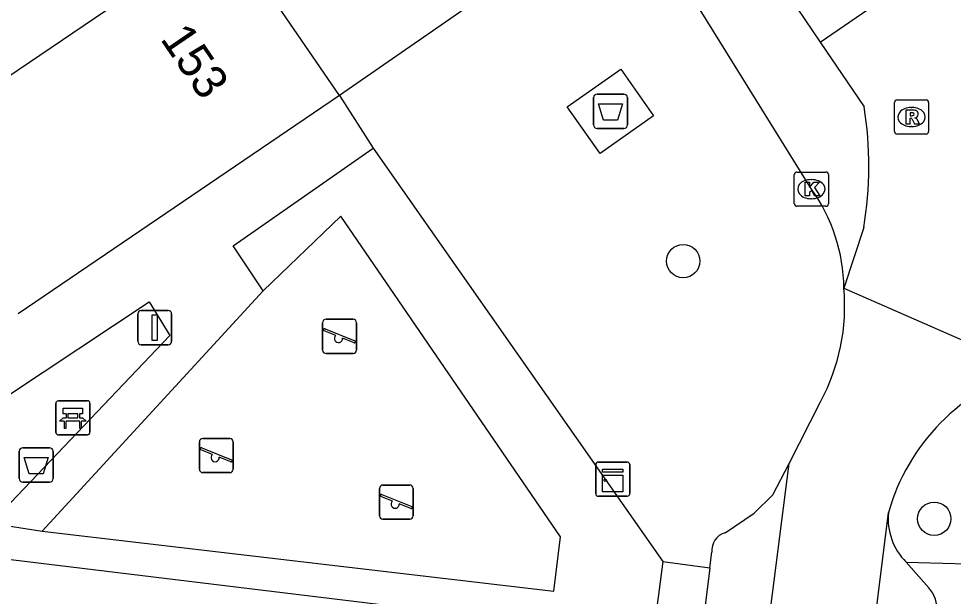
# Model space of a CAD drawing. Extents: x 158087 to 159494, y 382905 to 383981.
# Drawn here: x 158364.19 to 158391.56, y 383387.55 to 383404.47 of the extents above; entities that cross this region are included whole.
import ezdxf

# ---------------------------------------------------------------- set-up
doc = ezdxf.new("R2010")
doc.units = 0
for name, color, linetype in [('IMGEO_Afval_apart_plaats', 7, 'Continuous'), ('IMGEO_Afvalbak', 7, 'Continuous'), ('IMGEO_Bank', 7, 'Continuous'), ('IMGEO_Boom', 7, 'Continuous'), ('IMGEO_Groenvoorziening', 7, 'Continuous'), ('IMGEO_Kast', 7, 'Continuous'), ('IMGEO_Kolk', 7, 'Continuous'), ('IMGEO_Pand', 7, 'Continuous'), ('IMGEO_Pand_nummerreeks', 7, 'Continuous'), ('IMGEO_Rijbaan_lokaal_gesloten', 7, 'Continuous'), ('IMGEO_Rijbaan_lokaal_open', 7, 'Continuous'), ('IMGEO_Rioolput', 7, 'Continuous'), ('IMGEO_Speelvoorziening', 7, 'Continuous'), ('IMGEO_Verkeersbordpaal', 7, 'Continuous'), ('IMGEO_Voetpad_gesloten', 7, 'Continuous'), ('IMGEO_Voetpad_open', 7, 'Continuous')]:
    doc.layers.add(name, color=color, linetype=linetype)

msp = doc.modelspace()

# ---------------------------------------------------------------- linework, layer by layer
at = {"layer": 'IMGEO_Afval_apart_plaats'}
for p, q in [((158381.024, 383401.357), (158381.024, 383402.157)), ((158381.024, 383402.157), (158381.024, 383401.357)), ((158381.124, 383402.257), (158381.914, 383402.257)), ((158381.914, 383402.257), (158381.124, 383402.257)), ((158382.014, 383402.157), (158382.014, 383401.357)), ((158382.014, 383401.357), (158382.014, 383402.157)), ((158381.914, 383401.257), (158381.124, 383401.257)), ((158381.124, 383401.257), (158381.914, 383401.257))]:
    msp.add_line(p, q, dxfattribs=at)
msp.add_lwpolyline([(158381.167, 383401.971), (158381.871, 383401.971), (158381.722, 383401.501), (158381.316, 383401.501), (158381.167, 383401.971)], dxfattribs=at)
for centre, start, end in [((158381.124, 383402.157), 90, 180), ((158381.124, 383402.157), 90, 180), ((158381.914, 383402.157), 0, 90), ((158381.914, 383402.157), 360, 90), ((158381.124, 383401.357), 180, 270), ((158381.124, 383401.357), 180, 270), ((158381.914, 383401.357), 270, 0), ((158381.914, 383401.357), 270, 0)]:
    msp.add_arc(centre, 0.1, start, end, dxfattribs=at)
at = {"layer": 'IMGEO_Afvalbak'}
for p, q in [((158364.202, 383390.996), (158364.202, 383391.796)), ((158364.202, 383391.796), (158364.202, 383390.996)), ((158364.302, 383391.896), (158365.092, 383391.896)), ((158365.092, 383391.896), (158364.302, 383391.896)), ((158365.192, 383391.796), (158365.192, 383390.996)), ((158365.192, 383390.996), (158365.192, 383391.796)), ((158365.092, 383390.896), (158364.302, 383390.896)), ((158364.302, 383390.896), (158365.092, 383390.896))]:
    msp.add_line(p, q, dxfattribs=at)
msp.add_lwpolyline([(158364.345, 383391.61), (158365.049, 383391.61), (158364.9, 383391.14), (158364.494, 383391.14), (158364.345, 383391.61)], dxfattribs=at)
for centre, start, end in [((158364.302, 383391.796), 90, 180), ((158364.302, 383391.796), 90, 180), ((158365.092, 383391.796), 0, 90), ((158365.092, 383391.796), 360, 90), ((158364.302, 383390.996), 180, 270), ((158364.302, 383390.996), 180, 270), ((158365.092, 383390.996), 270, 0), ((158365.092, 383390.996), 270, 0)]:
    msp.add_arc(centre, 0.1, start, end, dxfattribs=at)
at = {"layer": 'IMGEO_Bank'}
for p, q in [((158365.272, 383392.351), (158365.272, 383393.192)), ((158365.272, 383393.192), (158365.272, 383392.351)), ((158365.347, 383393.276), (158366.188, 383393.276)), ((158366.188, 383393.276), (158365.347, 383393.276)), ((158366.272, 383393.201), (158366.272, 383392.36)), ((158366.272, 383392.36), (158366.272, 383393.201)), ((158365.581, 383392.782), (158365.581, 383392.888)), ((158365.625, 383392.888), (158365.625, 383392.782)), ((158365.913, 383392.894), (158365.631, 383392.894)), ((158365.919, 383392.782), (158365.919, 383392.888)), ((158365.963, 383392.888), (158365.963, 383392.782)), ((158365.969, 383392.674), (158365.576, 383392.674)), ((158365.631, 383392.776), (158365.913, 383392.776)), ((158366.197, 383392.276), (158365.356, 383392.276)), ((158365.356, 383392.276), (158366.197, 383392.276))]:
    msp.add_line(p, q, dxfattribs=at)
for points in [[(158365.575, 383392.894), (158365.489, 383392.894), (158365.489, 383393.055), (158366.052, 383393.055), (158366.052, 383392.894), (158365.969, 383392.894)], [(158365.519, 383392.674), (158365.377, 383392.674), (158365.489, 383392.776), (158365.575, 383392.776)], [(158365.569, 383392.667), (158365.569, 383392.46), (158365.526, 383392.46), (158365.526, 383392.667)], [(158365.969, 383392.776), (158366.052, 383392.776), (158366.164, 383392.674), (158366.025, 383392.674)], [(158366.019, 383392.667), (158366.019, 383392.46), (158365.975, 383392.46), (158365.975, 383392.667)]]:
    msp.add_lwpolyline(points, dxfattribs=at)
for centre, radius, start, end in [((158365.35, 383393.198), 0.0779, 92.4484, 184.2845), ((158365.35, 383393.198), 0.0779, 92.4484, 184.2845), ((158366.194, 383393.198), 0.0779, 2.4484, 94.2845), ((158366.194, 383393.198), 0.0779, 2.4484, 94.2845), ((158365.574, 383392.887), 0.00671, 2.8957, 87.1043), ((158365.631, 383392.887), 0.00671, 92.8957, 177.1043), ((158365.913, 383392.887), 0.00671, 2.8957, 87.1043), ((158365.97, 383392.887), 0.00671, 92.8957, 177.1043), ((158365.519, 383392.667), 0.00671, 2.8957, 87.1043), ((158365.576, 383392.667), 0.00671, 92.8957, 177.1043), ((158365.574, 383392.783), 0.00671, 272.8957, 357.1043), ((158365.631, 383392.783), 0.00671, 182.8957, 267.1043), ((158365.913, 383392.783), 0.00671, 272.8957, 357.1043), ((158365.97, 383392.783), 0.00671, 182.8957, 267.1043), ((158365.968, 383392.667), 0.00671, 2.8957, 87.1043), ((158366.025, 383392.667), 0.00671, 92.8957, 177.1043), ((158365.35, 383392.354), 0.0779, 182.4484, 274.2845), ((158365.35, 383392.354), 0.0779, 182.4484, 274.2845), ((158366.194, 383392.354), 0.0779, 272.4484, 4.2845), ((158366.194, 383392.354), 0.0779, 272.4484, 4.2845)]:
    msp.add_arc(centre, radius, start, end, dxfattribs=at)
at = {"layer": 'IMGEO_Boom'}
for centre in [(158383.648, 383397.369), (158391.001, 383389.819)]:
    msp.add_circle(centre, 0.489, dxfattribs=at)
at = {"layer": 'IMGEO_Groenvoorziening'}
msp.add_lwpolyline([(158364.869, 383389.459), (158379.856, 383387.7), (158380.054, 383389.292), (158373.623, 383398.689), (158371.344, 383396.5)], dxfattribs=at)
at = {"layer": 'IMGEO_Kast'}
for p, q in [((158381.161, 383391.481), (158382.002, 383391.481)), ((158382.002, 383391.481), (158381.161, 383391.481)), ((158381.086, 383390.556), (158381.086, 383391.397)), ((158381.086, 383391.397), (158381.086, 383390.556)), ((158382.086, 383391.406), (158382.086, 383390.565)), ((158382.086, 383390.565), (158382.086, 383391.406)), ((158382.011, 383390.481), (158381.17, 383390.481)), ((158381.17, 383390.481), (158382.011, 383390.481))]:
    msp.add_line(p, q, dxfattribs=at)
for points in [[(158381.281, 383391.271), (158381.881, 383391.271), (158381.881, 383391.186), (158381.281, 383391.186), (158381.281, 383391.271)], [(158381.281, 383391.096), (158381.881, 383391.096), (158381.881, 383390.607), (158381.281, 383390.607), (158381.281, 383391.096)]]:
    msp.add_lwpolyline(points, dxfattribs=at)
msp.add_circle((158381.365, 383390.945), 0.0377, dxfattribs=at)
for centre, start, end in [((158381.164, 383391.403), 92.4484, 184.2845), ((158381.164, 383391.403), 92.4484, 184.2845), ((158382.008, 383391.403), 2.4484, 94.2845), ((158382.008, 383391.403), 2.4484, 94.2845), ((158381.164, 383390.559), 182.4484, 274.2845), ((158381.164, 383390.559), 182.4484, 274.2845), ((158382.008, 383390.559), 272.4484, 4.2845), ((158382.008, 383390.559), 272.4484, 4.2845)]:
    msp.add_arc(centre, 0.0779, start, end, dxfattribs=at)
at = {"layer": 'IMGEO_Kolk'}
for p, q in [((158386.978, 383399.976), (158387.83, 383399.976)), ((158386.903, 383399.05), (158386.903, 383399.902)), ((158387.391, 383399.756), (158387.416, 383399.756)), ((158387.904, 383399.902), (158387.904, 383399.05)), ((158387.414, 383399.196), (158387.389, 383399.196)), ((158387.83, 383398.976), (158386.978, 383398.976))]:
    msp.add_line(p, q, dxfattribs=at)
for points in [[(158386.978, 383399.976), (158387.83, 383399.976)], [(158386.903, 383399.05), (158386.903, 383399.902)], [(158387.904, 383399.902), (158387.904, 383399.05)], [(158387.224, 383399.676), (158387.347, 383399.676), (158387.347, 383399.525), (158387.477, 383399.676), (158387.641, 383399.676), (158387.495, 383399.525), (158387.648, 383399.276), (158387.496, 383399.276), (158387.411, 383399.44), (158387.347, 383399.373), (158387.347, 383399.276), (158387.224, 383399.276), (158387.224, 383399.676)], [(158387.83, 383398.976), (158386.978, 383398.976)]]:
    msp.add_lwpolyline(points, dxfattribs=at)
for centre, start, end in [((158386.98, 383399.9), 91.552, 178.448), ((158386.98, 383399.9), 91.552, 178.448), ((158387.828, 383399.9), 1.552, 88.448), ((158387.828, 383399.9), 1.552, 88.448), ((158386.98, 383399.052), 181.552, 268.448), ((158386.98, 383399.052), 181.552, 268.448), ((158387.828, 383399.052), 271.552, 358.448), ((158387.828, 383399.052), 271.552, 358.448)]:
    msp.add_arc(centre, 0.0765, start, end, dxfattribs=at)
for centre, major_axis, ratio, start_param, end_param in [((158387.39, 383399.476), (-0.387, 0.002), 0.722429, 4.712389, 7.853982), ((158387.415, 383399.476), (-0.39, 0.002), 0.717154, 1.570796, 4.712389)]:
    msp.add_ellipse(centre, major_axis=major_axis, ratio=ratio, start_param=start_param, end_param=end_param, dxfattribs=at)
at = {"layer": 'IMGEO_Pand'}
for points in [[(158362.89, 383402.113), (158370.246, 383407.093)], [(158373.579, 383402.215), (158370.246, 383407.093)], [(158373.579, 383402.215), (158364.168, 383395.827)]]:
    msp.add_lwpolyline(points, dxfattribs=at)
at = {"layer": 'IMGEO_Rijbaan_lokaal_gesloten'}
for points in [[(158376.95, 383419.335), (158377.778, 383418.395), (158387.664, 383403.781)], [(158387.664, 383403.781), (158391.54, 383406.45)], [(158387.664, 383403.781), (158388.948, 383401.883)], [(158388.936, 383398.348), (158388.354, 383396.576)], [(158388.354, 383396.576), (158393.787, 383394.193)]]:
    msp.add_lwpolyline(points, dxfattribs=at)
msp.add_arc((158378.281, 383400.152), 10.807, 350.3922, 9.2188, dxfattribs=at)
at = {"layer": 'IMGEO_Rijbaan_lokaal_open'}
for points in [[(158386.755, 383391.434), (158387.668, 383393.247)], [(158379.524, 383334.921), (158386.755, 383391.434)], [(158382.338, 383331.19), (158389.661, 383390.001)]]:
    msp.add_lwpolyline(points, dxfattribs=at)
for centre, radius, start, end in [((158382.524, 383396.042), 5.854, 331.4801, 5.2322), ((158395.528, 383388.353), 6.094, 106.5991, 164.3101)]:
    msp.add_arc(centre, radius, start, end, dxfattribs=at)
at = {"layer": 'IMGEO_Rioolput'}
for p, q in [((158389.836, 383401.164), (158389.836, 383402.016)), ((158389.911, 383402.09), (158390.763, 383402.09)), ((158390.837, 383402.016), (158390.837, 383401.164)), ((158390.324, 383401.87), (158390.349, 383401.87)), ((158390.763, 383401.09), (158389.911, 383401.09)), ((158390.347, 383401.31), (158390.322, 383401.31))]:
    msp.add_line(p, q, dxfattribs=at)
for points in [[(158389.836, 383401.164), (158389.836, 383402.016)], [(158389.911, 383402.09), (158390.763, 383402.09)], [(158390.837, 383402.016), (158390.837, 383401.164)], [(158390.425, 383401.788), (158390.173, 383401.79), (158390.173, 383401.39)], [(158390.351, 383401.709), (158390.297, 383401.709), (158390.297, 383401.628)], [(158390.297, 383401.628), (158390.349, 383401.628)], [(158390.173, 383401.39), (158390.297, 383401.39), (158390.297, 383401.552), (158390.308, 383401.552)], [(158390.355, 383401.523), (158390.426, 383401.39), (158390.566, 383401.39), (158390.501, 383401.516)], [(158390.763, 383401.09), (158389.911, 383401.09)]]:
    msp.add_lwpolyline(points, dxfattribs=at)
for centre, radius, start, end in [((158389.913, 383402.014), 0.0765, 91.552, 178.448), ((158389.913, 383402.014), 0.0765, 91.552, 178.448), ((158390.761, 383402.014), 0.0765, 1.552, 88.448), ((158390.761, 383402.014), 0.0765, 1.552, 88.448), ((158390.333, 383401.817), 0.19, 274.7715, 282.9687), ((158390.357, 383401.613), 0.0964, 77.0061, 93.1865), ((158390.371, 383401.67), 0.0378, 276.6634, 79.6772), ((158390.424, 383401.678), 0.109, 350.3612, 89.416), ((158390.422, 383401.678), 0.112, 277.5842, 350.9817), ((158390.307, 383401.499), 0.0533, 26.0293, 88.6989), ((158390.406, 383401.463), 0.108, 29.5134, 73.7905), ((158389.913, 383401.166), 0.0765, 181.552, 268.448), ((158389.913, 383401.166), 0.0765, 181.552, 268.448), ((158390.761, 383401.166), 0.0765, 271.552, 358.448), ((158390.761, 383401.166), 0.0765, 271.552, 358.448)]:
    msp.add_arc(centre, radius, start, end, dxfattribs=at)
for centre, major_axis, ratio, start_param, end_param in [((158390.323, 383401.59), (-0.387, 0.002), 0.722429, 4.712389, 7.853982), ((158390.348, 383401.59), (-0.39, 0.002), 0.717154, 1.570796, 4.712389)]:
    msp.add_ellipse(centre, major_axis=major_axis, ratio=ratio, start_param=start_param, end_param=end_param, dxfattribs=at)
at = {"layer": 'IMGEO_Speelvoorziening'}
for p, q in [((158373.188, 383395.663), (158373.978, 383395.663)), ((158373.978, 383395.663), (158373.188, 383395.663)), ((158373.088, 383394.763), (158373.088, 383395.563)), ((158373.088, 383395.563), (158373.088, 383394.763)), ((158373.471, 383395.191), (158373.132, 383395.328)), ((158373.157, 383395.388), (158374.033, 383395.035)), ((158374.078, 383395.563), (158374.078, 383394.763)), ((158374.078, 383394.763), (158374.078, 383395.563)), ((158374.009, 383394.975), (158373.669, 383395.112)), ((158373.978, 383394.663), (158373.188, 383394.663)), ((158373.188, 383394.663), (158373.978, 383394.663)), ((158369.477, 383391.272), (158369.477, 383392.072)), ((158369.477, 383392.072), (158369.477, 383391.272)), ((158369.577, 383392.172), (158370.367, 383392.172)), ((158370.367, 383392.172), (158369.577, 383392.172)), ((158370.467, 383392.072), (158370.467, 383391.272)), ((158370.467, 383391.272), (158370.467, 383392.072)), ((158369.86, 383391.7), (158369.521, 383391.837)), ((158369.546, 383391.897), (158370.422, 383391.544)), ((158370.398, 383391.484), (158370.058, 383391.621)), ((158370.367, 383391.172), (158369.577, 383391.172)), ((158369.577, 383391.172), (158370.367, 383391.172)), ((158374.751, 383389.908), (158374.751, 383390.708)), ((158374.751, 383390.708), (158374.751, 383389.908)), ((158374.851, 383390.808), (158375.641, 383390.808)), ((158375.641, 383390.808), (158374.851, 383390.808)), ((158375.741, 383390.708), (158375.741, 383389.908)), ((158375.741, 383389.908), (158375.741, 383390.708)), ((158375.134, 383390.336), (158374.795, 383390.473)), ((158374.82, 383390.533), (158375.696, 383390.18)), ((158375.672, 383390.12), (158375.332, 383390.257)), ((158375.641, 383389.808), (158374.851, 383389.808)), ((158374.851, 383389.808), (158375.641, 383389.808))]:
    msp.add_line(p, q, dxfattribs=at)
for centre, radius, start, end in [((158373.188, 383395.563), 0.1, 90, 180), ((158373.188, 383395.563), 0.1, 90, 180), ((158373.978, 383395.563), 0.1, 0, 90), ((158373.978, 383395.563), 0.1, 360, 90), ((158373.145, 383395.358), 0.0327, 68.078, 248.078), ((158373.55, 383395.101), 0.12, 130.9928, 5.1632), ((158373.188, 383394.763), 0.1, 180, 270), ((158373.188, 383394.763), 0.1, 180, 270), ((158373.978, 383394.763), 0.1, 270, 0), ((158373.978, 383394.763), 0.1, 270, 0), ((158374.021, 383395.005), 0.0327, 248.078, 68.078), ((158369.577, 383392.072), 0.1, 90, 180), ((158369.577, 383392.072), 0.1, 90, 180), ((158370.367, 383392.072), 0.1, 0, 90), ((158370.367, 383392.072), 0.1, 360, 90), ((158369.534, 383391.867), 0.0327, 68.078, 248.078), ((158369.939, 383391.61), 0.12, 130.9928, 5.1632), ((158370.41, 383391.514), 0.0327, 248.078, 68.078), ((158369.577, 383391.272), 0.1, 180, 270), ((158369.577, 383391.272), 0.1, 180, 270), ((158370.367, 383391.272), 0.1, 270, 0), ((158370.367, 383391.272), 0.1, 270, 0), ((158374.851, 383390.708), 0.1, 90, 180), ((158374.851, 383390.708), 0.1, 90, 180), ((158375.641, 383390.708), 0.1, 0, 90), ((158375.641, 383390.708), 0.1, 360, 90), ((158374.808, 383390.503), 0.0327, 68.078, 248.078), ((158375.213, 383390.246), 0.12, 130.9928, 5.1632), ((158375.684, 383390.15), 0.0327, 248.078, 68.078), ((158374.851, 383389.908), 0.1, 180, 270), ((158374.851, 383389.908), 0.1, 180, 270), ((158375.641, 383389.908), 0.1, 270, 0), ((158375.641, 383389.908), 0.1, 270, 0)]:
    msp.add_arc(centre, radius, start, end, dxfattribs=at)
at = {"layer": 'IMGEO_Verkeersbordpaal'}
for p, q in [((158367.774, 383395.919), (158368.564, 383395.919)), ((158368.564, 383395.919), (158367.774, 383395.919)), ((158367.674, 383395.019), (158367.674, 383395.819)), ((158367.674, 383395.819), (158367.674, 383395.019)), ((158368.664, 383395.819), (158368.664, 383395.019)), ((158368.664, 383395.019), (158368.664, 383395.819)), ((158368.564, 383394.919), (158367.774, 383394.919)), ((158367.774, 383394.919), (158368.564, 383394.919))]:
    msp.add_line(p, q, dxfattribs=at)
msp.add_lwpolyline([(158368.094, 383395.794), (158368.244, 383395.794), (158368.244, 383395.044), (158368.094, 383395.044), (158368.094, 383395.794)], dxfattribs=at)
for centre, start, end in [((158367.774, 383395.819), 90, 180), ((158367.774, 383395.819), 90, 180), ((158368.564, 383395.819), 0, 90), ((158368.564, 383395.819), 360, 90), ((158367.774, 383395.019), 180, 270), ((158367.774, 383395.019), 180, 270), ((158368.564, 383395.019), 270, 0), ((158368.564, 383395.019), 270, 0)]:
    msp.add_arc(centre, 0.1, start, end, dxfattribs=at)
at = {"layer": 'IMGEO_Voetpad_gesloten'}
msp.add_lwpolyline([(158381.212, 383400.523), (158380.253, 383401.89), (158381.818, 383402.986), (158382.776, 383401.619), (158381.212, 383400.523)], dxfattribs=at)
at = {"layer": 'IMGEO_Voetpad_open'}
for points in [[(158349.641, 383444.76), (158358.306, 383437.257), (158379.659, 383406.433), (158373.579, 383402.215)], [(158387.404, 383399.476), (158379.654, 383411.978)], [(158373.579, 383402.215), (158374.569, 383400.679)], [(158371.344, 383396.5), (158370.464, 383397.815), (158374.569, 383400.679)], [(158374.569, 383400.679), (158383.052, 383388.57)], [(158364.869, 383389.459), (158371.344, 383396.5)], [(158382.756, 383386.327), (158360.813, 383388.997), (158359.701, 383390.67), (158368.002, 383396.172), (158368.608, 383395.193), (158363.371, 383389.695), (158364.869, 383389.459)], [(158384.875, 383389.409), (158385.727, 383389.988), (158386.272, 383390.516), (158386.755, 383391.434)], [(158384.428, 383388.384), (158384.485, 383388.837)], [(158383.052, 383388.57), (158382.756, 383386.327)], [(158383.052, 383388.57), (158384.428, 383388.384)], [(158390.177, 383388.549), (158393.042, 383388.471)], [(158390.177, 383388.549), (158390.838, 383387.796)], [(158384.428, 383388.384), (158383.916, 383384.305), (158378.092, 383337.858)]]:
    msp.add_lwpolyline(points, dxfattribs=at)
for centre, radius, start, end in [((158383.296, 383396.525), 5.059, 0.5832, 35.693), ((158391.445, 383389.817), 1.793, 174.1187, 225.0089), ((158385.034, 383388.882), 0.551, 106.7895, 184.6368), ((158390.256, 383387.219), 0.82, 350.4409, 44.7333)]:
    msp.add_arc(centre, radius, start, end, dxfattribs=at)

# ---------------------------------------------------------------- texts
at = {"layer": 'IMGEO_Pand_nummerreeks'}
msp.add_text('153', height=1, rotation=304.3257, dxfattribs=at).set_placement((158368.311, 383403.878))

doc.saveas('drawing.dxf')
